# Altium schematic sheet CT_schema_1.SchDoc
size 394 x 258 mm
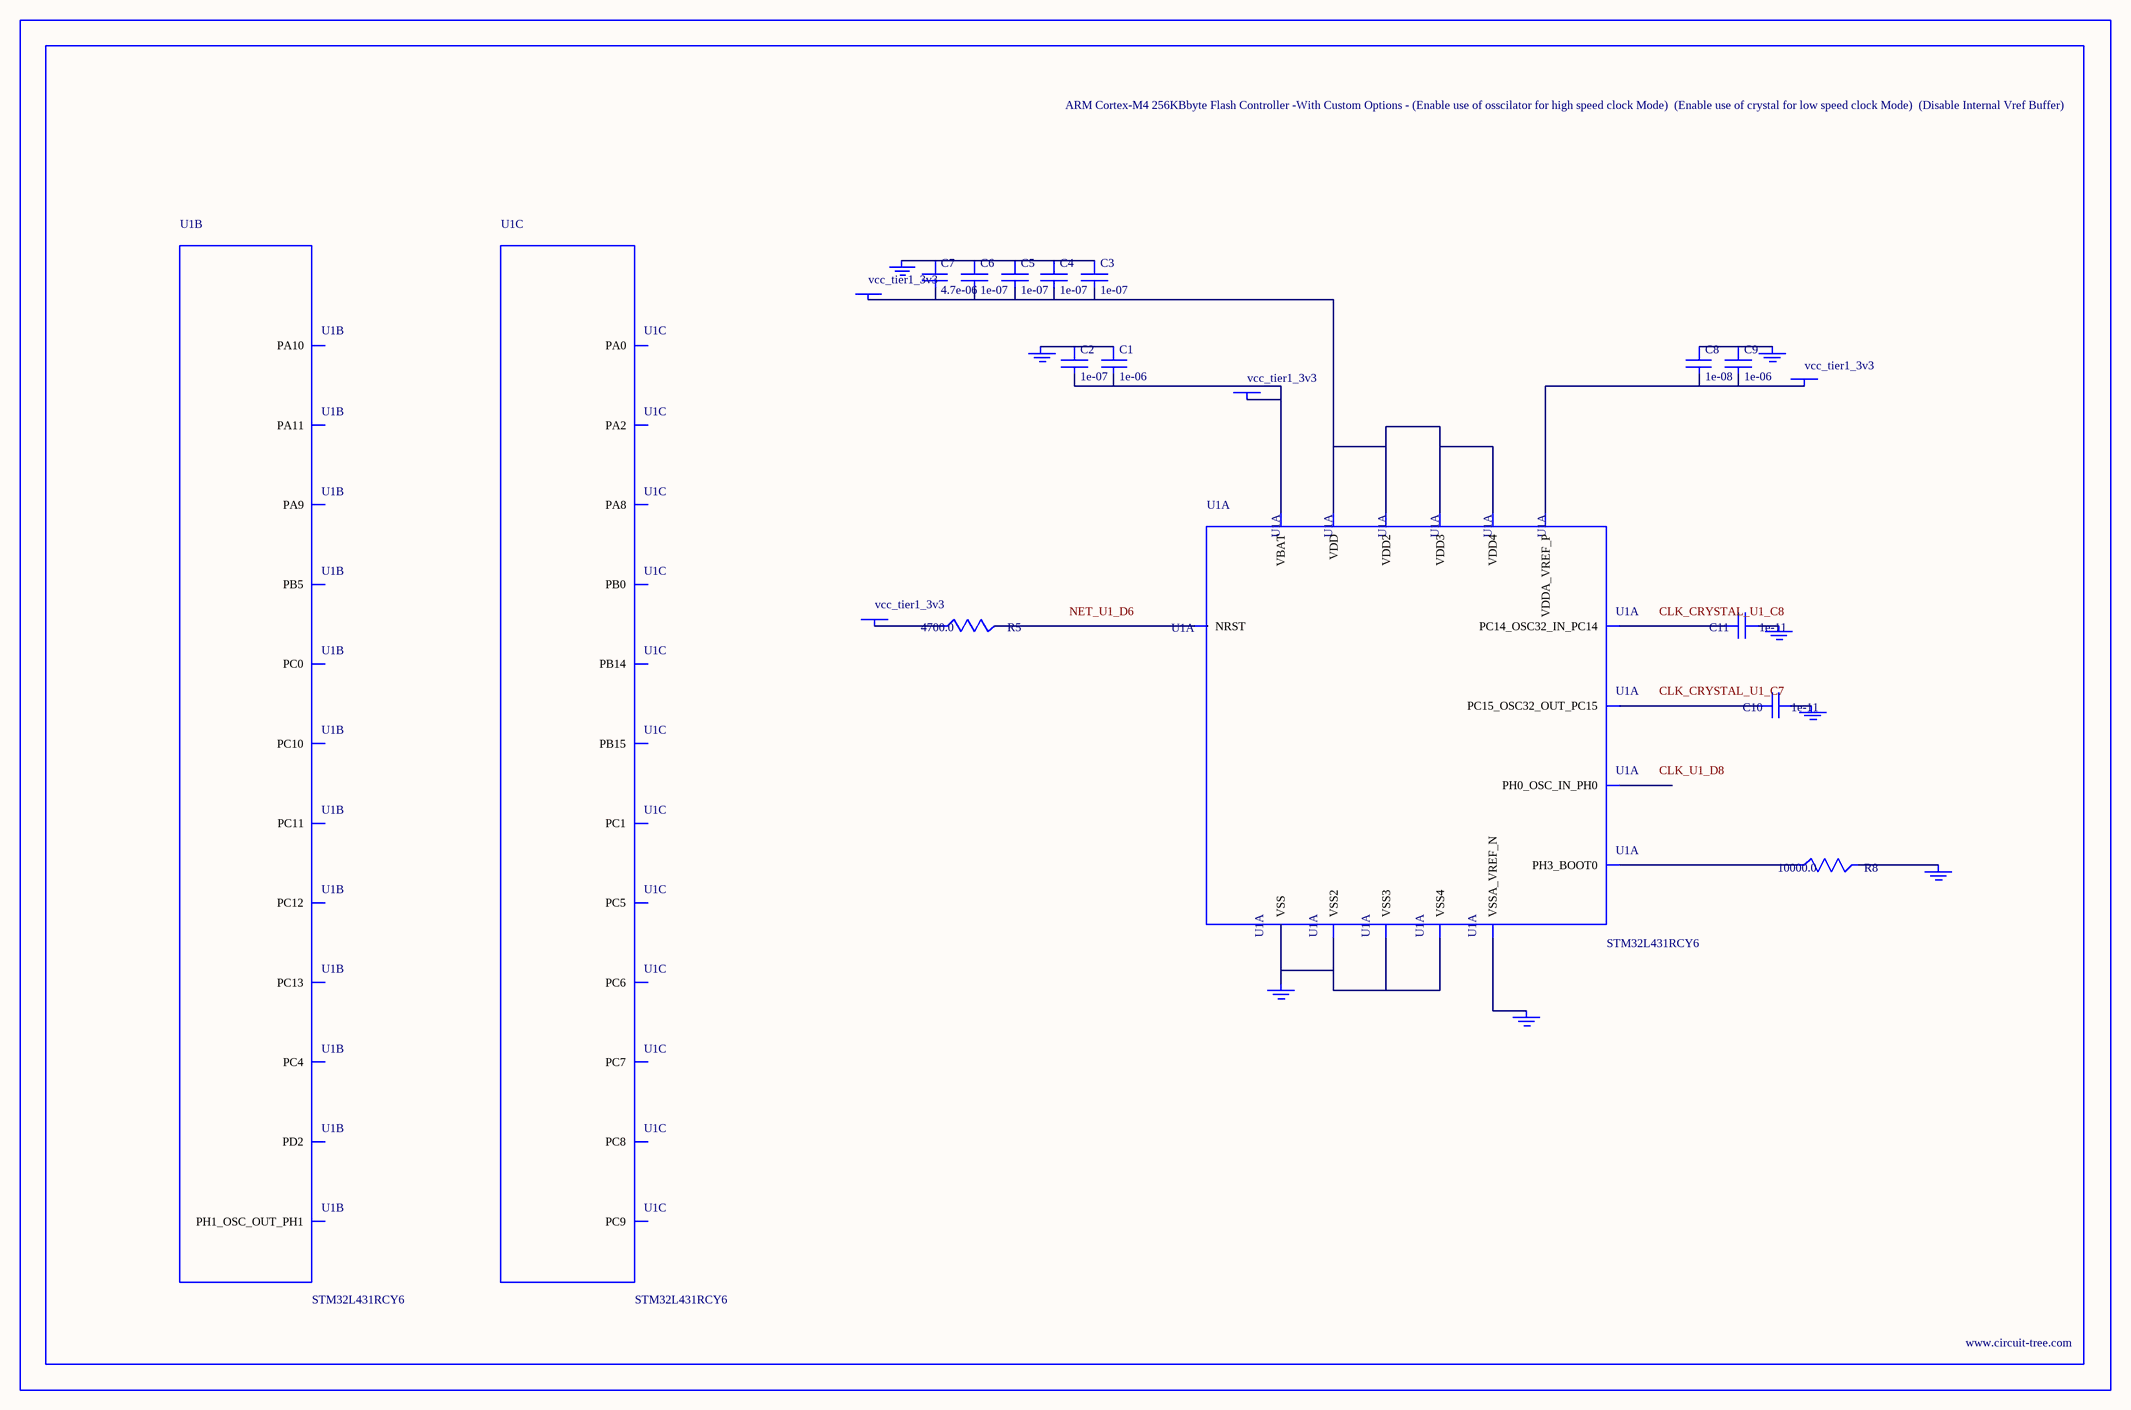
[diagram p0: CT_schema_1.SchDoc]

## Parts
BORDER0  (no value)
C1  1e-06  [C0603]
C2  1e-07  [C0603]
C3  1e-07  [C0603]
C4  1e-07  [C0603]
C5  1e-07  [C0603]
C6  1e-07  [C0603]
C7  4.7e-06  [C0603]
C8  1e-08  [C0603]
C9  1e-06  [C0603]
C10  1e-11  [C0402]
C11  1e-11  [C0402]
GND_INSTANCE_0_0  (no value)
GND_INSTANCE_0_1  (no value)
GND_INSTANCE_0_2  (no value)
GND_INSTANCE_0_3  (no value)
GND_INSTANCE_0_4  (no value)
GND_INSTANCE_0_5  (no value)
GND_INSTANCE_0_6  (no value)
GND_INSTANCE_0_7  (no value)
POWER_INSTANCE_0_0  vcc_tier1_3v3
POWER_INSTANCE_0_1  vcc_tier1_3v3
POWER_INSTANCE_0_2  vcc_tier1_3v3
POWER_INSTANCE_0_3  vcc_tier1_3v3
R5  4700.0  [R0603]
R8  10000.0  [R0603]
U1  STM32L431RCY6  [WLCSP64]  (parts A,B,C of 8)

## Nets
NetC1_1: C1.1 C2.1 GND_INSTANCE_0_0.0(GND)
NetC1_2: C1.2 C2.2 POWER_INSTANCE_0_0.0(PWR) U1.B7(VBAT)
NetC3_1: C3.1 C4.1 C5.1 C6.1 C7.1 GND_INSTANCE_0_1.0(GND)
NetC3_2: C3.2 C4.2 C5.2 C6.2 C7.2 POWER_INSTANCE_0_1.0(PWR) U1.A1(VDD) U1.A8(VDD2) U1.H1(VDD3) U1.H7(VDD4)
NetC8_1: C8.1 C9.1 GND_INSTANCE_0_3.0(GND)
NetC8_2: C8.2 C9.2 POWER_INSTANCE_0_2.0(PWR) U1.G8(VDDA_VREF_P)
NetC10_1: C10.1 GND_INSTANCE_0_4.0(GND)
NetC10_2: C10.2 U1.C7(PC15_OSC32_OUT_PC15)
NetC11_1: C11.1 GND_INSTANCE_0_5.0(GND)
NetC11_2: C11.2 U1.C8(PC14_OSC32_IN_PC14)
NetGND_INSTANCE_0_2_0: GND_INSTANCE_0_2.0(GND) R8.2
NetGND_INSTANCE_0_6_0: GND_INSTANCE_0_6.0(GND) U1.F8(VSSA_VREF_N)
NetGND_INSTANCE_0_7_0: GND_INSTANCE_0_7.0(GND) U1.A7(VSS) U1.B1(VSS2) U1.H2(VSS3) U1.H8(VSS4)
NetPOWER_INSTANCE_0_3_0: POWER_INSTANCE_0_3.0(PWR) R5.1
NetR5_2: R5.2 U1.D6(NRST)
NetR8_1: R8.1 U1.C5(PH3_BOOT0)

Not connected (* = marked no-connect by the designer): U1 A3(PC12) A4(PD2) B3(PC11) B8(PC13) C3(PC10) C4(PB5) D1(PA9) D2(PA10) D3(PA11) D4(PC4) D5(PC0) D7(PH1_OSC_OUT_PH1) D8(PH0_OSC_IN_PH0) E1(PC7) E2(PC9) E3(PA8) E4(PC5) E8(PC1) F1(PC6) F2(PB15) F3(PC8) F4(PB0) F6(PA2) F7(PA0) G1(PB14)

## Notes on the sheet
- Labels drawn without touching a wire or pin: CLK_CRYSTAL_U1_C7, CLK_CRYSTAL_U1_C8, CLK_U1_D8, NET_U1_D6

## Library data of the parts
BORDER0 = BORDER_PAGE0
C1 C9 = C0603C105K3RACTU
C2-C6 = 06035C104K4Z2A
C7 = GRM188R6YA475KE15D
C8 = 06035C103K4Z2A
C10 C11 = C0402C100K3GACTU
GND_INSTANCE_0_0-GND_INSTANCE_0_7 = GND
POWER_INSTANCE_0_0-POWER_INSTANCE_0_3 = PWR
R5 = RC0603JR-074K7L
R8 = RC0603JR-0710KL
